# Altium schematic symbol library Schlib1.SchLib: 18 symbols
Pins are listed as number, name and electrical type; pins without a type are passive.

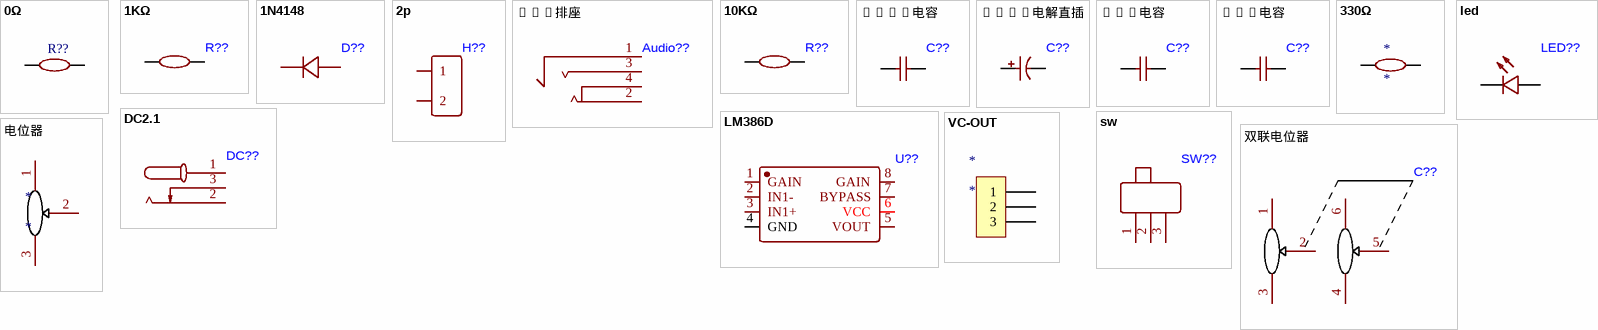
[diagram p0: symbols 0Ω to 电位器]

## 0Ω
designator R??
footprint R0805
pins: 1, 2

## 1KΩ
designator R??
footprint R0805
pins: 1, 2

## 1N4148
designator D??
footprint SOD-123_L3.1-W1.7-LS3.7-RD
pins: 1 K, 2 A

## 2p
designator H??
footprint HDR-TH_2P-P2.54-V-M-1
pins: 1, 2

## 3.5排座
designator Audio??
footprint 3.5排座
pins: 1, 2, 3, 4

## 10KΩ
designator R??
footprint R0805
pins: 1, 2

## 10uF电容
designator C??
footprint C0805
pins: 1, 2

## 10uF电解直插
designator C??
footprint CAP-TH_BD4.0-P1.50-D0.8-FD
pins: 1, 2

## 104电容
designator C??
footprint C0805
pins: 1, 2

## 224电容
designator C??
footprint C0805
pins: 1, 2

## 330Ω
designator *
footprint R0805
pins: 1, 2

## DC2.1
designator DC??
footprint DC-IN-TH_DC-470-2.1GP
pins: 1, 2, 3

## led
designator LED??
footprint LED0805-R-RD
pins: 1 A, 2 C

## LM386D
designator U??
footprint SOP-8_L4.9-W3.9-P1.27-LS6.0-BL
pins: 1 GAIN, 2 IN1-, 3 IN1+, 4 GND, 5 VOUT, 6 VCC, 7 BYPASS, 8 GAIN

## sw
designator SW??
footprint SW
pins: 1, 2, 3

## VC-OUT
designator *
footprint VC-OUT
pins: 1, 2, 3

## 双联电位器
designator C??
footprint 双联电位器
pins: 1, 2, 3, 4, 5, 6

## 电位器
designator *
footprint 电位器
pins: 1, 2, 3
